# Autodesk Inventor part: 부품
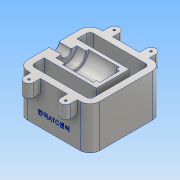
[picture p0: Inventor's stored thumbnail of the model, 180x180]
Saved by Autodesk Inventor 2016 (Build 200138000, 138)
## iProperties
Created: 2018-01
Part Number: 부품
Material: 알루미늄 6061
Document SubType Name: Modeling
Designer: Administrator
Density: 2.7 g/cm^3
Appearance: 알루미늄 - 평지
Mass: 1035.04 g
Surface Area: 788.468 cm^2
Volume: 383.348 cm^3
Author: Administrator
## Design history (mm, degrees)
sketch "스케치1"
  geometry: L1 (-55, 55)-(55, 55); L2 (55, 55)-(55, -55); L3 (55, -55)-(-55, -55); L4 (-55, -55)-(-55, 55); L5 (-55, 55)-(55, -55); L6 (55, 55)-(-55, -55); 1 further point
  constraints: 12 end point, 2 midpoint, 2 parallel, 1 horizontal, 1 perpendicular
  dimensions: "d0" = 110 distance of L1.start L1.end; "d1" = 110 distance of L1.end L2.end
extrude "돌출1" new body sketch "스케치1" distance "d2" = 65; taper "d3" = 0 deg
sketch "스케치2"
  geometry: L1 (55, 55)-(-55, 55) reference; L2 (-55, 55)-(-55, -55) reference; L3 (-55, -55)-(55, -55) reference; L4 (55, -55)-(55, 55) reference; L5 (-45, 45)-(-45, 25); L6 (-45, 25)-(35, 25); L7 (35, 25)-(35, -25); L8 (35, -25)-(-45, -25); L9 (-45, -25)-(-45, -45); L10 (-45, -45)-(45, -45); L11 (45, -45)-(45, 45); L12 (45, 45)-(-45, 45); 1 further point
  constraints: 16 end point, 6 perpendicular, 2 point on line, 1 vertical
  dimensions: "d4" = 30 distance between parallel lines of L1 L6; "d5" = 10 distance between parallel lines of L2 L5; "d6" = 20 distance between parallel lines of L4 L7; "d7" = 10 distance between parallel lines of L4 L11; "d8" = 10 distance between parallel lines of L1 L12; "d9" = 10 distance between parallel lines of L3 L10; "d10" = 30 distance between parallel lines of L3 L8
extrude "돌출2" cut sketch "스케치2" stored distance "d11" = 65; taper "d12" = 0 deg
sketch "스케치3"
  geometry: L1 (55, 55)-(-55, 55) reference; L2 (-55, 55)-(-55, -55) reference; L3 (-35.5, 65)-(-20.5, 65); L4 (-20.5, 65)-(-20.5, 55); L5 (-20.5, 55)-(-35.5, 55); L6 (-35.5, 55)-(-35.5, 65); L7 (-35.5, 65)-(-20.5, 55); L8 (-20.5, 65)-(-35.5, 55); L9 (0, 0)-(0, 92.754); L10 (20.5, 55)-(35.5, 55); L11 (35.5, 65)-(20.5, 65); L12 (20.5, 65)-(20.5, 55); L13 (35.5, 65)-(20.5, 55); L14 (20.5, 65)-(35.5, 55); L15 (35.5, 55)-(35.5, 65); A1 r 7.5 centre (-28, 65) between (-20.5, 65) and (-35.5, 65); A2 r 7.5 centre (28, 65) between (35.5, 65) and (20.5, 65); 2 further points
  constraints: 26 end point, 6 symmetric about line, 5 midpoint, 4 point on circle, 2 centre point, 2 parallel, 1 horizontal, 1 perpendicular, 1 point on line, 1 vertical, 1 other
  dimensions: "d13" = 27 distance from line of L2 A1.centre; "d14" = 7.5 radius of A1; "d15" = 10 distance between parallel lines of L1 L3
extrude "돌출3" join sketch "스케치3" distance "d16" = 20; taper "d17" = 0 deg
fillet "모깎기1" dims "d27" = 15
fillet "모깎기2" dims "d28" = 5
sketch "스케치8"
  geometry: L1 (45, -25)-(-35, -25); L2 (-35, -25)-(-35, 25); L3 (-35, 25)-(45, 25); L4 (45, 25)-(45, -25); 1 further point
  constraints: 8 end point, 2 parallel, 1 horizontal, 1 perpendicular
extrude "돌출4" cut sketch "스케치8" stored distance "d33" = 45; taper "d34" = 0 deg
sketch "스케치11"
  geometry: L1 (-55, -40)-(-55, 40) reference; L2 (-55, 25)-(35, 25); L3 (35, 25)-(35, -25); L4 (35, -25)-(-55, -25); L5 (-55, -25)-(-55, 25); 2 further points
  constraints: 8 end point, 2 parallel, 1 horizontal, 1 horizontal alignment, 1 midpoint, 1 perpendicular, 1 point on line
  dimensions: "d45" = 90 distance of L2.start L2.end; "d46" = 50 distance of L2.end L3.end
extrude "돌출5" join sketch "스케치11" stored distance "d47" = 40; taper "d48" = 0 deg
sketch "스케치12"
  geometry: L1 (-55, 40)-(-55, -40) reference; L2 (-55, 0)-(70.588, 0); L3 (-55, 0)-(-55, 7.5); L4 (-55, 7.5)-(-36, 7.5); L5 (-36, 7.5)-(-36, 16); L6 (-36, 16)-(-22, 16); L7 (-22, 16)-(-22, 20); L8 (-22, 20)-(25, 20); L9 (25, 20)-(25, 15); L10 (25, 15)-(30, 15); L11 (30, 15)-(30, 0); 1 further point
  constraints: 20 end point, 7 perpendicular, 2 horizontal, 2 point on line, 1 midpoint
  dimensions: "d49" = 15 diameter of L4 L2; "d50" = 19 distance of L3.end L4.end; "d51" = 14 distance of L5.end L6.end; "d52" = 32 diameter of L6 L2; "d53" = 40 diameter of L8 L2; "d54" = 30 diameter of L10 L2; "d55" = 47 distance of L7.end L8.end; "d56" = 5 distance of L9.end L10.end
revolve "회전2" sketch "스케치12" stored, may be unused: angle "d57" = 180 deg
sketch "스케치15"
  geometry: A1 r 7.5 centre (-28, -65) between (-35.5, -65) and (-20.5, -65) reference; A2 r 7.5 centre (28, -65) between (20.5, -65) and (35.5, -65) reference; A3 r 7.5 centre (28, 65) between (35.5, 65) and (20.5, 65) reference; A4 r 7.5 centre (-28, 65) between (-20.5, 65) and (-35.5, 65) reference; 5 further points
  constraints: 4 coincident
hole "구멍1" sketch "스케치15" at (-28, -65), (28, -65), (28, 65), (-28, 65) diameter "d66" = 3.242; stored, may be unused: countersink angle "d70" = 90 deg, drill point angle "d72" = 118 deg; dims "d67" = 9, "d68" = 4, "d69" = 2, "d71" = 11
sketch "스케치16" dims "d0" = 110, "d1" = 110
  geometry: L1 (60.5, -65)-(-19.5, -65) reference; L2 (-34.5, 0)-(-34.5, -65) reference; 2 further points
  constraints: 1 other
  dimensions: "d77" = 20 distance from line of L1 point (20.5, -45); "d78" = 55 distance from line of L2 point (20.5, -45)
feature "엠보싱1" sketch "스케치16" dims "d0" = 110, "d1" = 110, "d79" = 0.5, "d80" = 0
fillet "모깎기7" dims "d81" = 1
chamfer "모따기1" distance "d82" = 1; stored, may be unused: second distance "d83" = 2, angle "d84" = 45 deg
sketch "스케치19"
  geometry: L1 (-35, 65)-(-35, 0) reference; L2 (-35, 30)-(45, 8.564); L3 (45, 8.564)-(45, 0); L4 (40, 0)-(-40, 0) reference; L5 (55, 0)-(55, 65) reference; L6 (-35, 30)-(-35, 0); L7 (-32, 0)-(-32, 65) reference; L8 (45, 0)-(-35, 0); 1 further point
  constraints: 8 end point, 2 point on line, 1 collinear, 1 parallel, 1 vertical
  dimensions: "d85" = 105 deg angle of L3 L2; "d86" = 30 distance from line of L4 L2.start; "d87" = 10 distance between parallel lines of L5 L3
extrude "돌출7" cut sketch "스케치19" stored distance "d88" = 40; taper "d89" = 0 deg
sketch "스케치20"
  geometry: L1 (55, 0)-(55, 65) reference; L2 (55, 11.061)-(-20, 31.157); L3 (55, 29.061)-(17, 39.243); L4 (17, 39.243)-(17, 45); L5 (-24, 45)-(22, 45) reference; L6 (-35, 30)-(45, 8.564) reference; L7 (-20, 31.157)-(-20, 45); L8 (-25, 65)-(-25, 46) reference; 1 further point
  constraints: 8 end point, 4 point on line, 1 parallel, 1 perpendicular, 1 vertical
  dimensions: "d90" = 75 deg angle of L1 L3; "d92" = 5 distance between parallel lines of L6 L2; "d93" = 18 distance of L2.start L3.start; "d94" = 37 distance between parallel lines of L7 L4; "d95" = 5 distance between parallel lines of L8 L7
extrude "돌출8" join sketch "스케치20" stored distance "d96" = 18; taper "d97" = 0 deg
node "솔리드1"
mirror "대칭1"
